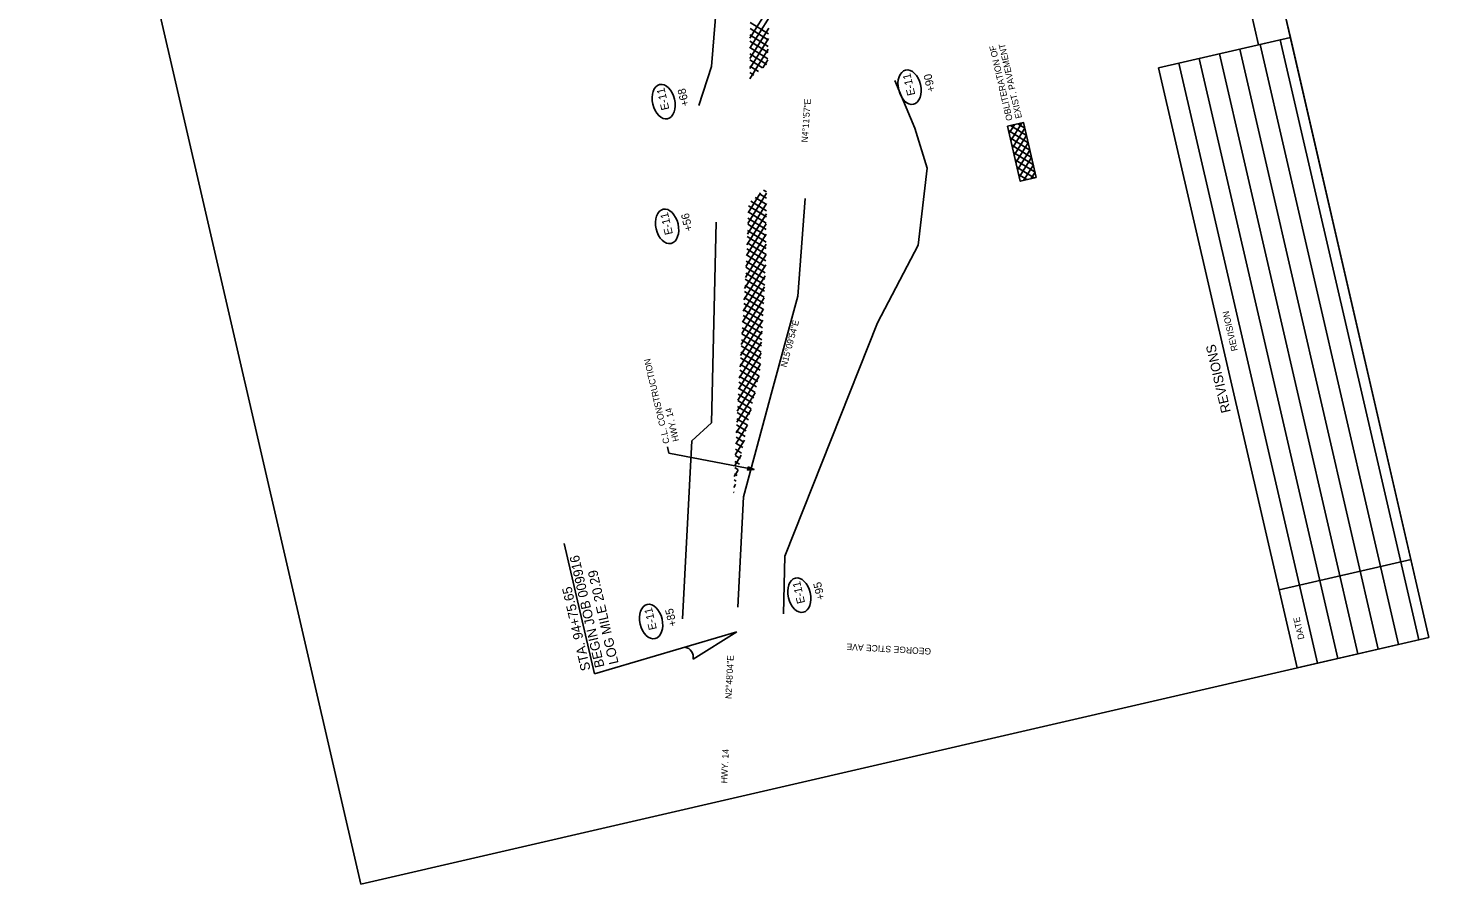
# Model space of a CAD drawing. Extents: x 634644 to 1109343, y 286699 to 700411.
# Drawn here: x 1108030 to 1109343, y 698620 to 699423 of the extents above; entities that cross this region are included whole.
import ezdxf

# ---------------------------------------------------------------- set-up
doc = ezdxf.new("R2010")
doc.units = 0
for name, color, linetype in [('53', 7, 'Continuous'), ('S_BASELINE', 7, 'Continuous'), ('S_BASELINE_ANNOT', 7, 'Continuous'), ('S_EXIST_ROW', 7, 'Continuous'), ('S_GUARDRAIL', 7, 'Continuous'), ('S_PRIMARY_CTL', 7, 'Continuous'), ('S_RDW_PT_SYM', 7, 'Continuous'), ('S_SECONDARY_CTL', 7, 'Continuous'), ('S_STR_PT_SYM', 7, 'Continuous'), ('S_WATER_UTILITIES', 7, 'Continuous'), ('XSEC_P_Ditch-and-Channel-Line', 7, 'Continuous')]:
    doc.layers.add(name, color=color, linetype=linetype)

msp = doc.modelspace()

# ---------------------------------------------------------------- linework, layer by layer
at = {"layer": '53'}
for p, q in [((1109213.4, 699413.9), (1109089.9, 699385.4)), ((1109333.7, 698849.1), (1109203.9, 699411.7)), ((1109343.2, 698851.3), (1109213.4, 699413.9)), ((1109276.7, 698836), (1109146.9, 699398.6)), ((1109295.7, 698840.3), (1109165.9, 699403)), ((1109314.7, 698844.7), (1109184.9, 699407.4)), ((1109219.7, 698822.8), (1109089.9, 699385.4)), ((1109238.7, 698827.2), (1109108.9, 699389.8)), ((1109257.7, 698831.6), (1109127.9, 699394.2)), ((1109326.4, 698924.4), (1109202.9, 698895.9)), ((1109343.2, 698851.3), (1109219.7, 698822.8))]:
    msp.add_line(p, q, dxfattribs=at)
at = {"layer": 'S_BASELINE'}
msp.add_lwpolyline([(1109343.2, 698851.3), (1108342.3, 698620.2), (1108052.7, 699874.6), (1108100.8, 699885.7), (1108030.4, 700190.9), (1108983.2, 700410.8)], close=True, dxfattribs=at)
at = {"layer": 'S_EXIST_ROW'}
for p, q in [((1108700.8, 698983.1), (1108727.8, 699082.9)), ((1108695.7, 698879.8), (1108700.8, 698983.1))]:
    msp.add_line(p, q, dxfattribs=at)
msp.add_lwpolyline([(1108727.8, 699082.9), (1108751.8, 699171.4), (1108758.5, 699262.8)], dxfattribs=at)
at = {"layer": 'S_PRIMARY_CTL'}
for p, q in [((1109183.6, 699407.1), (1109138.7, 699601.6)), ((1109168.5, 699608.4), (1109213.4, 699413.9)), ((1109213.4, 699413.9), (1109183.6, 699407.1))]:
    msp.add_line(p, q, dxfattribs=at)
at = {"layer": 'S_RDW_PT_SYM'}
for p, q in [((1108706.9, 699413.3), (1108725.2, 699442.6)), ((1108706.9, 699403.8), (1108724.9, 699432.6)), ((1108724.4, 699417.2), (1108707, 699428.1)), ((1108706.7, 699384.7), (1108724.3, 699412.8)), ((1108706.8, 699394.3), (1108724.6, 699422.7)), ((1108724.1, 699405.6), (1108706.9, 699416.3)), ((1108724.2, 699411.4), (1108707, 699422.2)), ((1108706.7, 699375.2), (1108724, 699402.9)), ((1108722.8, 699388.7), (1108706.8, 699398.7)), ((1108723.9, 699399.8), (1108706.9, 699410.4)), ((1108723.7, 699394), (1108706.9, 699404.6)), ((1108718.8, 699385.3), (1108706.8, 699392.8)), ((1108714.8, 699381.9), (1108706.8, 699386.9)), ((1108719, 699385.5), (1108723.7, 699393)), ((1108710.7, 699378.6), (1108706.7, 699381.1)), ((1108951.4, 699317.3), (1108961.6, 699333.7)), ((1108964.5, 699328.9), (1108958.1, 699332.9)), ((1108967.7, 699315.1), (1108949.2, 699326.7)), ((1108949.8, 699324.2), (1108954.7, 699332.1)), ((1108969.3, 699308.2), (1108950.8, 699319.8)), ((1108966.1, 699322), (1108951.2, 699331.3)), ((1108952.9, 699310.4), (1108964.5, 699328.9)), ((1108954.5, 699303.5), (1108966.1, 699322.1)), ((1108970.9, 699301.3), (1108952.4, 699312.9)), ((1108956.1, 699296.6), (1108967.7, 699315.2)), ((1108957.7, 699289.7), (1108969.3, 699308.3)), ((1108972.5, 699294.4), (1108954, 699306)), ((1108974.1, 699287.5), (1108955.5, 699299.1)), ((1108959.3, 699282.9), (1108970.9, 699301.4)), ((1108963.3, 699279.9), (1108972.5, 699294.5)), ((1108973.3, 699282.2), (1108957.1, 699292.2)), ((1108966.4, 699280.6), (1108958.7, 699285.3)), ((1108970.2, 699281.5), (1108974.1, 699287.6)), ((1108704.8, 699239.6), (1108722.4, 699267.8)), ((1108705.2, 699249.6), (1108716.9, 699268.3)), ((1108722.4, 699263.2), (1108715.8, 699267.3)), ((1108722.5, 699269.1), (1108719.7, 699270.8)), ((1108704.5, 699229.6), (1108722.4, 699258.3)), ((1108722.3, 699245.6), (1108705.4, 699256.1)), ((1108722.3, 699251.4), (1108707.8, 699260.5)), ((1108722.4, 699257.3), (1108711.8, 699263.9)), ((1108704.1, 699219.6), (1108722.3, 699248.7)), ((1108722.2, 699233.8), (1108705, 699244.6)), ((1108722.2, 699239.7), (1108705.2, 699250.4)), ((1108703.2, 699199.2), (1108722.2, 699229.6)), ((1108703.7, 699209.4), (1108722.2, 699239.2)), ((1108722.1, 699222.1), (1108704.6, 699233)), ((1108722.2, 699228), (1108704.8, 699238.8)), ((1108702.6, 699188.8), (1108722.1, 699220)), ((1108721.9, 699204.5), (1108704, 699215.8)), ((1108722, 699210.4), (1108704.2, 699221.5)), ((1108722.1, 699216.2), (1108704.4, 699227.3)), ((1108701.9, 699178.4), (1108722, 699210.5)), ((1108721.3, 699193.1), (1108703.4, 699204.3)), ((1108721.6, 699198.8), (1108703.7, 699210)), ((1108700.6, 699157.4), (1108721.2, 699190.3)), ((1108701.3, 699167.9), (1108721.7, 699200.6)), ((1108720.7, 699181.7), (1108702.9, 699192.9)), ((1108721, 699187.4), (1108703.1, 699198.6)), ((1108700, 699146.9), (1108720.6, 699180)), ((1108719.8, 699164.6), (1108701.8, 699175.8)), ((1108720.1, 699170.3), (1108702.1, 699181.5)), ((1108720.4, 699176), (1108702.5, 699187.2)), ((1108699.4, 699136.5), (1108720.1, 699169.7)), ((1108719.2, 699153.2), (1108701.1, 699164.5)), ((1108719.5, 699158.9), (1108701.4, 699170.2)), ((1108698.7, 699126.1), (1108719.5, 699159.3)), ((1108718.6, 699141.8), (1108700.4, 699153.1)), ((1108718.9, 699147.5), (1108700.7, 699158.8)), ((1108697.5, 699105.2), (1108718.4, 699138.6)), ((1108698.1, 699115.6), (1108719, 699149)), ((1108717.6, 699124.7), (1108699.3, 699136.1)), ((1108717.9, 699130.4), (1108699.7, 699141.8)), ((1108718.3, 699136.1), (1108700, 699147.5)), ((1108696.8, 699094.6), (1108717.8, 699128.3)), ((1108717, 699113.3), (1108698.7, 699124.7)), ((1108717.3, 699119), (1108699, 699130.4)), ((1108696.1, 699084.1), (1108717.3, 699118)), ((1108716.4, 699101.9), (1108698, 699113.4)), ((1108716.7, 699107.6), (1108698.3, 699119)), ((1108695, 699063.5), (1108715.6, 699096.5)), ((1108695.5, 699073.7), (1108716.7, 699107.6)), ((1108714.4, 699091.3), (1108697.3, 699102)), ((1108715.6, 699096.4), (1108697.7, 699107.7)), ((1108710.6, 699076), (1108696.1, 699085)), ((1108711.8, 699081.1), (1108696.5, 699090.7)), ((1108713.1, 699086.2), (1108696.9, 699096.4)), ((1108694.5, 699053.3), (1108711.8, 699080.8)), ((1108708, 699065.8), (1108695.5, 699073.6)), ((1108709.3, 699070.9), (1108695.8, 699079.4)), ((1108694, 699043.1), (1108707.9, 699065.2)), ((1108705.6, 699055.5), (1108695, 699062.2)), ((1108706.8, 699060.7), (1108695.2, 699067.9)), ((1108693.6, 699032.9), (1108704.6, 699050.5)), ((1108702.4, 699039.9), (1108694.1, 699045)), ((1108703.5, 699045.1), (1108694.4, 699050.7)), ((1108704.5, 699050.3), (1108694.7, 699056.5)), ((1108693.1, 699022.7), (1108701.7, 699036.4)), ((1108700.2, 699029.4), (1108693.6, 699033.6)), ((1108701.3, 699034.6), (1108693.9, 699039.3)), ((1108692.6, 699012.5), (1108698.7, 699022.3)), ((1108698.1, 699019), (1108693.1, 699022.1)), ((1108699.1, 699024.2), (1108693.3, 699027.8)), ((1108692.2, 699002.3), (1108695.8, 699008.2)), ((1108695, 699003.2), (1108692.3, 699004.9)), ((1108695.9, 699008.5), (1108692.6, 699010.6)), ((1108697, 699013.8), (1108692.8, 699016.4)), ((1108691.7, 698992.1), (1108693.5, 698995.1)), ((1108693.1, 698992.6), (1108691.8, 698993.4)), ((1108694, 698997.9), (1108692, 698999.2)), ((1108692.2, 698987.3), (1108691.5, 698987.7))]:
    msp.add_line(p, q, dxfattribs=at)
msp.add_lwpolyline([(1108975.2, 699282.6), (1108963.3, 699334.1), (1108948.3, 699330.6), (1108960.2, 699279.1)], close=True, dxfattribs=at)
at = {"layer": 'S_SECONDARY_CTL'}
for p in [(1108629.5, 699030.2), (1108710.8, 699008.7)]:
    msp.add_line(p, (1108630.8, 699024.3), dxfattribs=at)
msp.add_lwpolyline([(1108705.2, 699011.3), (1108710.8, 699008.7), (1108704.7, 699008.3)], close=True, dxfattribs=at)
at = {"layer": 'S_STR_PT_SYM'}
for p, q in [((1108561.1, 698817.2), (1108532.9, 698939.5)), ((1108561.1, 698817.2), (1108694.6, 698856.6)), ((1108694.6, 698856.6), (1108653.6, 698831.1))]:
    msp.add_line(p, q, dxfattribs=at)
msp.add_arc((1108644.5, 698833.1), 9.29, 347.9602, 80.5032, dxfattribs=at)
at = {"layer": 'XSEC_P_Ditch-and-Channel-Line'}
for p, q in [((1108659.1, 699350), (1108670.8, 699386.6)), ((1108864.4, 699219.1), (1108873.1, 699291.4)), ((1108826.3, 699146.5), (1108864.4, 699219.1)), ((1108739.5, 698927.7), (1108826.3, 699146.5)), ((1108738.2, 698873.4), (1108739.5, 698927.7))]:
    msp.add_line(p, q, dxfattribs=at)
for points in [[(1108670.8, 699386.6), (1108679.1, 699486.6), (1108678.6, 699553.1), (1108664, 699679.3), (1108650.4, 699710.5), (1108634.8, 699734.8)], [(1108873.1, 699291.4), (1108861.3, 699328.9), (1108842.7, 699373.5)], [(1108643.7, 698868.8), (1108652.6, 699035.7), (1108670.8, 699052.5), (1108675.1, 699240.7)]]:
    msp.add_lwpolyline(points, dxfattribs=at)
for centre in [(1108856.5, 699367.3), (1108626, 699353.7), (1108629.3, 699236.8), (1108753.2, 698891), (1108614.3, 698866.3)]:
    msp.add_ellipse(centre, major_axis=(-3.7, 16), ratio=0.638788, dxfattribs=at)

# ---------------------------------------------------------------- texts
at = {"layer": '53'}
for s, p in [('REVISION', (1109164.1, 699120.6)), ('DATE', (1109226.6, 698850.2))]:
    msp.add_text(s, height=6, rotation=103, dxfattribs=at).set_placement(p)
at = {"layer": 'S_BASELINE_ANNOT'}
for s, rotation, p in [('N4%%d11\'57"E', 85.801, (1108761, 699315.3)), ('N15%%d09\'54"E', 74.8611, (1108741.2, 699104.2)), ('N2%%d48\'04"E', 87.199, (1108689.7, 698793.6))]:
    msp.add_text(s, height=6, rotation=rotation, dxfattribs=at).set_placement(p)
at = {"layer": 'S_GUARDRAIL'}
for s, rotation, p in [('GEORGE STICE AVE', 176.7646, (1108876.8, 698841.2)), ('HWY. 14', 87.1826, (1108685.6, 698714.5))]:
    msp.add_text(s, height=6, rotation=rotation, dxfattribs=at).set_placement(p)
at = {"layer": 'S_PRIMARY_CTL'}
for s, height, p in [('OBLITERATION OF', 6, (1108953.2, 699336.6)), ('EXIST. PAVEMENT', 6, (1108961.9, 699338.7)), ('REVISIONS', 9, (1109157.6, 699063))]:
    msp.add_text(s, height=height, rotation=103, dxfattribs=at).set_placement(p)
at = {"layer": 'S_SECONDARY_CTL'}
for s, p in [('C.L. CONSTRUCTION', (1108631.7, 699033.8)), ('HWY. 14', (1108640.5, 699035.8))]:
    msp.add_text(s, height=6, rotation=103, dxfattribs=at).set_placement(p)
at = {"layer": 'S_WATER_UTILITIES'}
for s, p in [('BEGIN JOB 009916', (1108570.7, 698824.2)), ('LOG MILE 20.29', (1108583.9, 698827.3)), ('STA. 94+75.65', (1108557.6, 698821.2))]:
    msp.add_text(s, height=9, rotation=103, dxfattribs=at).set_placement(p)
at = {"layer": 'XSEC_P_Ditch-and-Channel-Line'}
for s, p in [('E-11', (1108861.9, 699360.3)), ('+90', (1108880.6, 699363.8)), ('E-11', (1108631.4, 699346.7)), ('+68', (1108650, 699350.2)), ('E-11', (1108634.7, 699229.8)), ('+56', (1108653.3, 699233.2)), ('E-11', (1108758.6, 698884)), ('+95', (1108777.2, 698887.4)), ('E-11', (1108619.7, 698859.3)), ('+85', (1108638.4, 698862.6))]:
    msp.add_text(s, height=7.5, rotation=103.0379, dxfattribs=at).set_placement(p)

doc.saveas('drawing.dxf')
